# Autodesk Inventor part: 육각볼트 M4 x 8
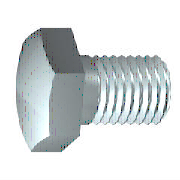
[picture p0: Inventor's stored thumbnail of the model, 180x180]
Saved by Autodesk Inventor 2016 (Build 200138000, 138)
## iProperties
Created: 2012-02
Part Number: 육각볼트 M4 x 8
Material: 강철, 연강
Description: 6각 머리 나사
Document SubType Name: Modeling
Standard: ISO 4017
Designer: mduedu
Standard Revision: Third edition 1999-08-15
Standards Organization: ISO
Language: ko-KR
Size Designation: M4 x 10
Categories: <MemberInstance><Categories><Category DisplayName="조임쇠" InternalName="e4da775c-781d-43d5-af7c-5136215cf5a6" Mnemonic="FSTN"><Category DisplayName="볼트" InternalN
Density: 7.86 g/cm^3
Appearance: 반광택
IsCustomPart: 0
Author: mduedu
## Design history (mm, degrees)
sketch "스케치1"
  geometry: L1 (0, 3.015)-(0, 2); L2 (1.75, 2)-(8, 2); L3 (8, 2)-(8, 0); L4 (8, 0)-(-0.4, 0); L5 (-2.08, 0)-(9.68, 0) reference; L6 (-0.4, 0)-(-0.4, 3.015); L7 (-0.4, 3.015)-(0, 3.015); L8 (1.75, 2)-(1.32, 2); L9 (1.32, 2)-(0, 2); L10 (0, -0.603)-(0, 3.618) reference
  constraints: 16 end point, 2 collinear, 2 perpendicular, 1 parallel
  dimensions: "d0" = 8 distance between parallel lines of L3 L1 (= NLG); "d1" = 6.25 distance from line of L2.start L3 (= GEL); "d2" = 4 diameter of L2 L4 (= GD); "d9" = 0.4001 distance between parallel lines of L6 L1 (computed from SD); "d10" = 6.03 diameter of L7 L4 (= SD2); "d13" = 0.42952 distance of L2.start L8.end (computed from GAL); "d14" = 4 diameter of L9 L4 (= BDM)
revolve "본체" sketch "스케치1" stored, may be unused: angle "d12" = 90 deg
sketch "스케치2"
  geometry: L1 (0, 4.041)-(3.5, 2.021); L2 (3.5, 2.021)-(3.5, -2.021); L3 (3.5, -2.021)-(0, -4.041); L4 (0, -4.041)-(-3.5, -2.021); L5 (-3.5, -2.021)-(-3.5, 2.021); L6 (-3.5, 2.021)-(0, 4.041); 2 further points
  constraints: 12 end point, 1 coincident, 1 vertical, 11 other
  dimensions: "d11" = 7 distance between parallel lines of L5 L2 (= SW)
extrude "머리" join sketch "스케치2" distance "d3" = 2.4 (= KOH - SD); taper "d4" = 0 deg
sketch "스케치4"
  geometry: L1 (-2.8, 3.5)-(-2.8, 4.041); L2 (-2.8, 4.041)-(-2.487, 4.041); L3 (-2.487, 4.041)-(-2.8, 3.5); L4 (-3.28, 0)-(0.08, 0) reference; L5 (-0.4, 4.041)-(-2.8, 4.041) reference; L6 (-2.8, 2.021)-(-2.8, 4.041) reference
  constraints: 6 end point, 2 collinear, 1 perpendicular, 1 vertical
  dimensions: "d5" = 30 deg angle of L3 L1 (= ANG1); "d19" = 7 diameter of L1.start L4 (= SW0)
revolve "모따기1" sketch "스케치4" stored, may be unused: angle "d21" = 90 deg
workplane "Work Plane1"
body "Solid1"
feature "스레드" dims "d15" = 6.25 (= GEL), "d16" = 0
chamfer "모따기2" distance "d6" = 0.42941 (= -0.5 x SPD + 0.5 x GD); stored, may be unused: second distance "d7" = 0.42952 (computed from GUL), angle "d55" = 45 deg
other parameters: "NLG" = 8 [user parameter; used in 1 equation term], "GD" = 4 (= NND) [user parameter; used in 2 equation terms], "BDM" = 4 (= NND) [user parameter; used in 1 equation term], "KOH" = 2.8 [user parameter; used in 1 equation term], "GEL" = 6.25 [user parameter; used in 2 equation terms], "SW" = 7 [user parameter; used in 2 equation terms], "SW0" = 7 (= SW) [user parameter; used in 1 equation term], "SPD" = 3.14117 (= NND - 1.2269 x PTC) [user parameter; used in 1 equation term], "SD2" = 6.03 [user parameter; used in 2 equation terms], "SD" = 0.4 [user parameter; used in 2 equation terms], "ANG1" = 30 deg [user parameter; used in 1 equation term], "GAL" = 0.42941 (= 0.61345 x PTC) [user parameter; used in 1 equation term], "GUL" = 0.42941 (= 0.61345 x PTC) [user parameter; used in 1 equation term], "d8" = 0, "RR" = 0.2 [user parameter], "d57" = 0, "d58" = 0, "TPU" = 14.28571 (computed from PTC) [user parameter], "GD1" = 3.14117 (= THREADDIA - 1.2269 x PTC) [user parameter], "THREADDIA" = 4 [user parameter; used in 1 equation term], "SDH" = 6.03 (= SD2) [user parameter], "SDHG" = 2.1 [user parameter], "TOA" = 30 deg [user parameter], "PTC" = 0.7 [user parameter; used in 5 equation terms], "NND" = 4 [user parameter; used in 3 equation terms], "E0" = 8.085 [user parameter]
